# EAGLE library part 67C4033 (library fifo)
FIFO
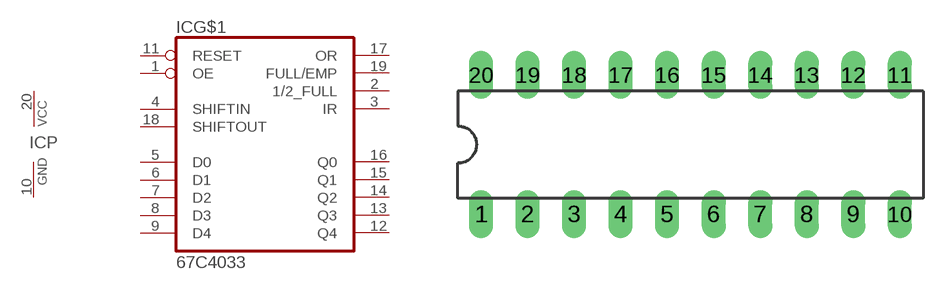
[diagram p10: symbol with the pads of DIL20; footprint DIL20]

Designator prefix IC; gates G$1=67C4033 P=PWRN

## 67C4033 (OC_FARNELL: unknown; OC_NEWARK: unknown)  [DIL20]
1  G$1:OE  in
2  G$1:1/2_FULL  out
3  G$1:IR  out
4  G$1:SHIFTIN  in
5  G$1:D0  in
6  G$1:D1  in
7  G$1:D2  in
8  G$1:D3  in
9  G$1:D4  in
10  P:GND  pwr
11  G$1:RESET  in
12  G$1:Q4  hiz
13  G$1:Q3  hiz
14  G$1:Q2  hiz
15  G$1:Q1  hiz
16  G$1:Q0  hiz
17  G$1:OR  out
18  G$1:SHIFTOUT  in
19  G$1:FULL/EMP  out
20  P:VCC  pwr

## Footprint DIL20 (pad centres in mm)
Dual In Line Package
drill 0.813 long: 1 -11.43,-3.81; 2 -8.89,-3.81; 3 -6.35,-3.81; 4 -3.81,-3.81; 5 -1.27,-3.81; 6 1.27,-3.81; 7 3.81,-3.81; 8 6.35,-3.81; 9 8.89,-3.81; 10 11.43,-3.81; 11 11.43,3.81; 12 8.89,3.81; 13 6.35,3.81; 14 3.81,3.81; 15 1.27,3.81; 16 -1.27,3.81; 17 -3.81,3.81; 18 -6.35,3.81; 19 -8.89,3.81; 20 -11.43,3.81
